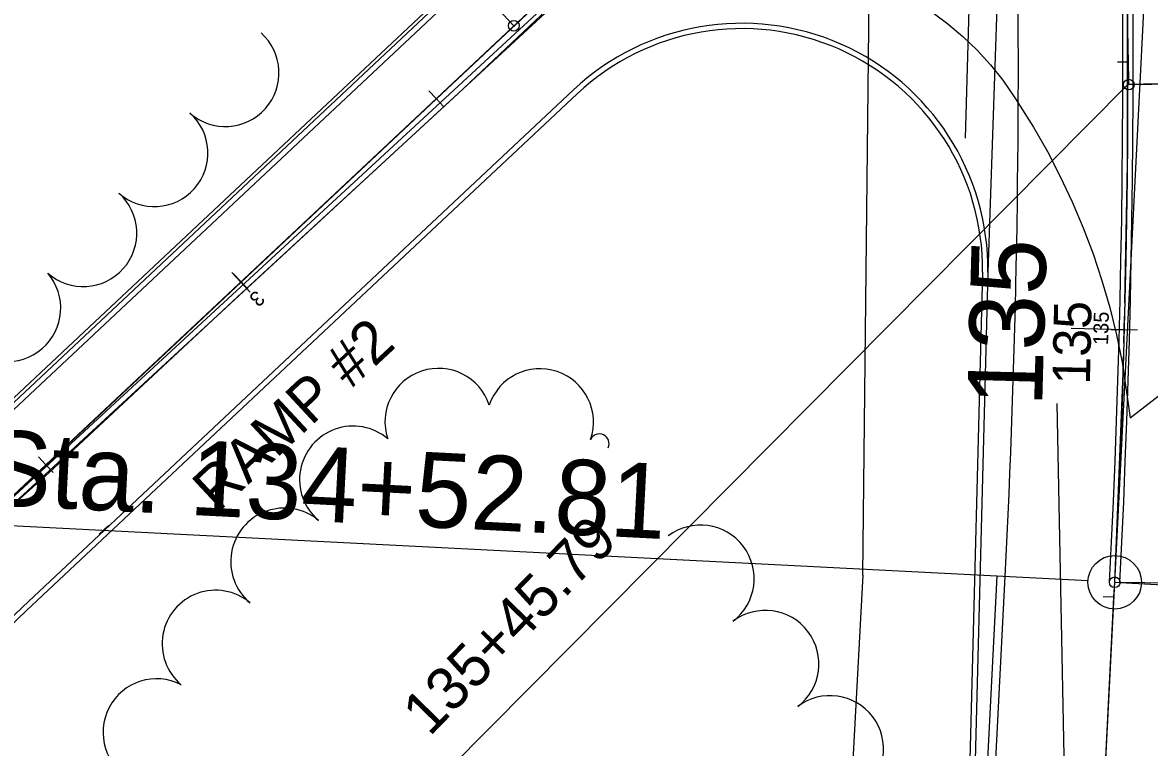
# Model space of a CAD drawing. Extents: x -25029 to 2274964, y -81170 to 687028.
# Drawn here: x -4191.7 to -3981.1, y -66307.8 to -66172.5 of the extents above; entities that cross this region are included whole.
import ezdxf

# ---------------------------------------------------------------- set-up
doc = ezdxf.new("R2010")
doc.units = 0
for name, color, linetype in [('81911BEA - RW_X_Fee_RW', 7, 'Continuous'), ('AP_X_Runway', 7, 'Continuous'), ('BD_X_Canopy', 7, 'Continuous'), ('Default', 7, 'Continuous'), ('GE_X_CL_100', 7, 'Continuous'), ('GE_X_CL_20', 7, 'Continuous'), ('GK_Visualization', 7, 'Continuous'), ('PM_P_CL_Double_Solid', 7, 'Continuous'), ('PM_P_Yield_Line', 7, 'Continuous'), ('PV_X_Curb', 7, 'Continuous'), ('PV_X_EOP', 7, 'Continuous'), ('RD_X_GR_Rt', 7, 'Continuous'), ('TREES', 7, 'Continuous')]:
    doc.layers.add(name, color=color, linetype=linetype)

msp = doc.modelspace()

# ---------------------------------------------------------------- linework, layer by layer
at = {"layer": '81911BEA - RW_X_Fee_RW'}
msp.add_line((-4034.71, -66275.66), (-4039.77, -66369.33), dxfattribs=at)
msp.add_lwpolyline([(-4034.71, -66275.66), (-4032.93, -66116.64), (-4044.75, -65958.04), (-4070.06, -65801.04), (-4108.7, -65646.77)], dxfattribs=at)
at = {"layer": 'AP_X_Runway'}
for p, q in [((-4045.24, -66105.82), (-4335.98, -66378.47)), ((-4191.69, -66281.55), (-4088.79, -66185.05)), ((-4011.32, -66219.09), (-4015.1, -66362.53)), ((-4012.53, -66362.66), (-4008.1, -66275.94))]:
    msp.add_line(p, q, dxfattribs=at)
for centre, radius, start, end in [((-5895, -66179.56), 1889.36, 357.076, 4.59193), ((-4057.32, -66218.6), 46, 359.4001, 133.1608), ((-4146.54, -66329.69), 66, 133.1608, 266.3388)]:
    msp.add_arc(centre, radius, start, end, dxfattribs=at)
at = {"layer": 'BD_X_Canopy'}
for p, q in [((-3987.63, -66276.99), (-3962.62, -65787.41)), ((-4099.92, -66173.06), (-4235.9, -66027.92)), ((-4369.84, -66425.97), (-3988.3, -66068.47)), ((-3985, -66184.06), (-3986.24, -66122.56)), ((-3985, -66184.06), (-3699.65, -66178.28)), ((-3994.85, -66418.3), (-3998.38, -66243.6)), ((-4033.13, -66736.6), (-4009.6, -66275.87)), ((-3994.85, -66418.3), (-3987.63, -66276.99)), ((-3987.63, -66276.99), (-3843.07, -66284.37))]:
    msp.add_line(p, q, dxfattribs=at)
msp.add_arc((-5895, -66179.56), 1909.86, 357.076, 25.8676, dxfattribs=at)
at = {"layer": 'Default'}
for p, q in [((-4406.23, -66460.38), (-3988.37, -66068.52)), ((-3988.37, -66068.52), (-4369.76, -66426.18)), ((-3699.16, -66178.04), (-3985.15, -66184.05)), ((-3699.16, -66178.04), (-3985.15, -66184.05)), ((-3985.15, -66184.05), (-4111.95, -66311.78)), ((-3985.15, -66184.05), (-3985.15, -66184.05)), ((-4152.64, -66219.14), (-4149.22, -66222.79)), ((-4150.93, -66220.97), (-4150.93, -66220.97)), ((-3988.37, -66229.77), (-3983.37, -66229.87)), ((-3985.8, -66229.83), (-3985.8, -66229.83)), ((-4053.51, -67566.81), (-3987.63, -66276.99)), ((-3987.63, -66276.99), (-3987.63, -66276.99)), ((-3987.63, -66276.99), (-3675.42, -66279.45))]:
    msp.add_line(p, q, dxfattribs=at)
for points in [[(-3985.24, -66179.83), (-3985.24, -66159.77), (-3985.76, -66134.83)], [(-4114.46, -66186.76), (-4081.64, -66155.98)], [(-3985.77, -66224.82), (-3985.24, -66198.85), (-3985.24, -66179.83)], [(-3951.89, -66183.35), (-3985.15, -66184.05)], [(-4147.28, -66217.55), (-4114.46, -66186.76)], [(-4152.76, -66222.68), (-4149.11, -66219.26)], [(-4187.4, -66255.17), (-4154.58, -66224.39)], [(-3985.92, -66232.32), (-3985.82, -66227.32)], [(-3987.77, -66279.78), (-3987.63, -66276.99), (-3987.63, -66276.99), (-3986.03, -66237.93), (-3985.97, -66234.82)], [(-4220.23, -66285.95), (-4187.4, -66255.17)], [(-3990.07, -66324.72), (-3987.77, -66279.78)]]:
    msp.add_lwpolyline(points, dxfattribs=at)
for radius in [1910.82, 1908.9, 1909.86]:
    msp.add_arc((-5895, -66179.56), radius, 357.076, 25.86759, dxfattribs=at)
at = {"layer": 'GE_X_CL_100'}
for p, q in [((-3985.8, -66229.83), (-3995.8, -66229.57)), ((-3992.62, -66276.73), (-4230.8, -66264.57)), ((-3992, -66362.55), (-3987.63, -66276.99))]:
    msp.add_line(p, q, dxfattribs=at)
for points in [[(-4088.16, -66164.72), (-4110.37, -66185.78), (-4151.55, -66223.69), (-4186.81, -66256.55), (-4220.49, -66286.59), (-4226.43, -66292.08)], [(-4021.78, -66170.47), (-4018.83, -66172.69), (-4016.01, -66175.08), (-4013.35, -66177.65), (-4010.86, -66180.37), (-4008.54, -66183.25), (-4006.2, -66186.68), (-4002.81, -66192.01), (-4000.21, -66196.56), (-3997.8, -66201.2), (-3995.57, -66205.94), (-3993.53, -66210.77), (-3991.68, -66215.67), (-3990.02, -66220.64), (-3988.57, -66225.67), (-3987.31, -66230.76), (-3986.26, -66235.89), (-3984.76, -66246.25)], [(-3984.76, -66246.25), (-3941.44, -66212.83), (-3936.77, -66209.29), (-3931.97, -66205.93), (-3927.05, -66202.75), (-3922, -66199.76), (-3916.85, -66196.97), (-3911.6, -66194.38), (-3906.25, -66192), (-3900.81, -66189.82), (-3894.62, -66187.64), (-3889.71, -66186.09), (-3884.06, -66184.55), (-3878.35, -66183.23), (-3872.61, -66182.13), (-3866.82, -66181.25), (-3861.01, -66180.6)]]:
    msp.add_lwpolyline(points, dxfattribs=at)
msp.add_circle((-3987.63, -66276.99), 5, dxfattribs=at)
msp.add_arc((-5895, -66179.56), 1909.86, 357.076, 25.8676, dxfattribs=at)
at = {"layer": 'GE_X_CL_20'}
for p, q in [((-3985.02, -66183.06), (-3986.4, -66115.11)), ((-3985.14, -66179.84), (-3987.14, -66179.84)), ((-4114.44, -66186.66), (-4115.8, -66185.2)), ((-4114.44, -66186.66), (-4113.07, -66188.12)), ((-4150.92, -66220.85), (-4152.29, -66219.39)), ((-4150.92, -66220.85), (-4149.56, -66222.31)), ((-3985.8, -66229.83), (-3987.8, -66229.78)), ((-4187.41, -66255.04), (-4188.78, -66253.58)), ((-4187.41, -66255.04), (-4186.04, -66256.5)), ((-3986.63, -66277.04), (-3919.11, -66280.49)), ((-3987.77, -66279.79), (-3989.77, -66279.69))]:
    msp.add_line(p, q, dxfattribs=at)
for centre in [(-4099.92, -66173.06), (-3985, -66184.06), (-3987.63, -66276.99)]:
    msp.add_circle(centre, 1, dxfattribs=at)
at = {"layer": 'GK_Visualization'}
for p, q in [((-4099.98, -66173.12), (-4099.85, -66172.99)), ((-4099.98, -66172.99), (-4099.85, -66173.12)), ((-3985.07, -66184.12), (-3984.93, -66183.99)), ((-3985.07, -66183.99), (-3984.93, -66184.12)), ((-3963, -66183.61), (-3985, -66184.06)), ((-3992, -66362.55), (-3987.63, -66276.99)), ((-3987.55, -66276.99), (-3987.71, -66276.99)), ((-3987.69, -66277.05), (-3987.56, -66276.92)), ((-3987.69, -66276.92), (-3987.56, -66277.05)), ((-3987.63, -66276.91), (-3987.63, -66277.07))]:
    msp.add_line(p, q, dxfattribs=at)
msp.add_arc((-5895, -66179.56), 1909.86, 357.076, 25.8676, dxfattribs=at)
msp.add_arc((-5895, -66179.56), 1909.86, 357.076, 25.8676, dxfattribs=at)
at = {"layer": 'PM_P_CL_Double_Solid'}
for p, q in [((-4226.77, -66291.71), (-4081.98, -66158.18)), ((-4226.07, -66292.43), (-4081.31, -66158.91))]:
    msp.add_line(p, q, dxfattribs=at)
at = {"layer": 'PM_P_Yield_Line'}
msp.add_line((-4014.57, -66158.09), (-4015.6, -66194.06), dxfattribs=at)
at = {"layer": 'PV_X_Curb'}
for p, q in [((-4045.92, -66105.1), (-4336.66, -66377.74)), ((-4088.1, -66185.78), (-4191, -66282.28)), ((-4012.32, -66219.06), (-4016.15, -66364.38))]:
    msp.add_line(p, q, dxfattribs=at)
for centre, radius, start, end in [((-4057.32, -66218.6), 45, 359.4001, 133.1608), ((-4146.54, -66329.69), 65, 133.1608, 266.3388)]:
    msp.add_arc(centre, radius, start, end, dxfattribs=at)
at = {"layer": 'PV_X_EOP'}
for p, q in [((-4045.24, -66105.82), (-4335.98, -66378.47)), ((-4009.27, -66157.58), (-4011.32, -66219.09)), ((-4088.79, -66185.05), (-4191.69, -66281.55)), ((-4011.32, -66219.09), (-4015.1, -66362.53))]:
    msp.add_line(p, q, dxfattribs=at)
msp.add_lwpolyline([(-4177.44, -66268.03), (-4175.69, -66266.37)], dxfattribs=at)
for centre, radius, start, end in [((-4057.32, -66218.6), 46, 359.4001, 133.1608), ((-4146.54, -66329.69), 66, 133.1608, 266.3388)]:
    msp.add_arc(centre, radius, start, end, dxfattribs=at)
at = {"layer": 'RD_X_GR_Rt'}
msp.add_line((-4046.35, -66104.64), (-4305.1, -66347.28), dxfattribs=at)
at = {"layer": 'TREES'}
for centre, radius, start, end in [((-4153.81, -66181.88), 10, 228.3785, 48.3785), ((-4167.1, -66196.83), 10, 228.3785, 48.3785), ((-4180.38, -66211.78), 10, 228.3785, 48.3785), ((-4194.6, -66225.78), 10, 220.731, 40.731), ((-4114, -66247.04), 10, 18.383, 198.383), ((-4095.04, -66247.1), 10, 341.2443, 161.2443), ((-4129.96, -66257.82), 10, 49.6998, 229.6998), ((-4083.94, -66251.1), 1.81, 334.4312, 154.4312), ((-4142.83, -66273.13), 10, 50.1975, 230.1975), ((-4065.01, -66276.31), 10, 307.2131, 127.2131), ((-4155.65, -66288.47), 10, 50.0354, 230.0354), ((-4052.92, -66292.24), 10, 307.2131, 127.2131), ((-4166.69, -66305.01), 10, 62.5158, 242.5158), ((-4040.82, -66308.16), 10, 307.2131, 127.2131)]:
    msp.add_arc(centre, radius, start, end, dxfattribs=at)

# ---------------------------------------------------------------- texts
at = {"layer": 'Default'}
for s, height, rotation, p in [('135', 7, 88.835, (-3992.27, -66240.13)), ('RAMP #2', 8, 42.9378, (-4155.23, -66264.09)), ('135+45.79', 8, 45.7535, (-4115.68, -66305.94))]:
    msp.add_text(s, height=height, rotation=rotation, dxfattribs=at).set_placement(p)
at = {"layer": 'GE_X_CL_100'}
for s, rotation, p in [('135', 88.4917, (-4001.19, -66244.26)), ('PC Sta. 134+52.81', 357.076, (-4230.31, -66260.83))]:
    msp.add_text(s, height=14, rotation=rotation, dxfattribs=at).set_placement(p)
at = {"layer": 'GE_X_CL_20'}
for s, rotation, p in [('3', 223.136, (-4148.08, -66222.3)), ('135', 88.4917, (-3988.88, -66232.72))]:
    msp.add_text(s, height=2.8, rotation=rotation, dxfattribs=at).set_placement(p)
at = {"layer": 'GK_Visualization'}
for s, p in [('141', (-4099.92, -66173.06)), ('113', (-3985, -66184.06)), ('126', (-3987.63, -66276.99))]:
    msp.add_text(s, height=0.14, dxfattribs=at).set_placement(p)

doc.saveas('drawing.dxf')
